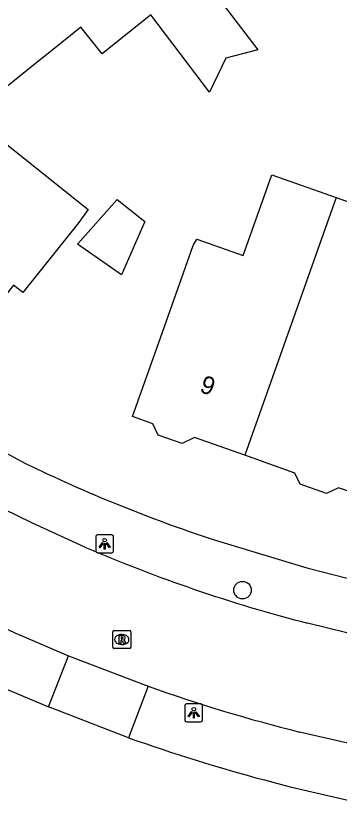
# Model space of a CAD drawing. Extents: x 161354 to 161876, y 382161 to 382804.
# Drawn here: x 161529.82 to 161547.84, y 382263.36 to 382307.76 of the extents above; entities that cross this region are included whole.
import ezdxf

# ---------------------------------------------------------------- set-up
doc = ezdxf.new("R2010")
doc.units = 0
for name, color, linetype in [('IMGEO_Boom', 7, 'Continuous'), ('IMGEO_Lichtpunt', 7, 'Continuous'), ('IMGEO_Pand', 7, 'Continuous'), ('IMGEO_Pand_nummerreeks', 7, 'Continuous'), ('IMGEO_Rijbaan_lokaal_open', 7, 'Continuous'), ('IMGEO_Rioolput', 7, 'Continuous'), ('IMGEO_Voetpad_open', 7, 'Continuous')]:
    doc.layers.add(name, color=color, linetype=linetype)

msp = doc.modelspace()

# ---------------------------------------------------------------- linework, layer by layer
at = {"layer": 'IMGEO_Boom'}
msp.add_circle((161542.46, 382275.697), 0.489, dxfattribs=at)
at = {"layer": 'IMGEO_Lichtpunt'}
for p, q in [((161534.268, 382278.688), (161534.268, 382277.881)), ((161534.268, 382278.688), (161534.268, 382277.881)), ((161535.17, 382278.783), (161534.362, 382278.783)), ((161535.17, 382278.783), (161534.362, 382278.783)), ((161535.264, 382277.881), (161535.264, 382278.688)), ((161535.264, 382277.881), (161535.264, 382278.688)), ((161534.362, 382277.787), (161535.17, 382277.787)), ((161534.362, 382277.787), (161535.17, 382277.787)), ((161540.14, 382269.341), (161539.332, 382269.341)), ((161540.14, 382269.341), (161539.332, 382269.341)), ((161539.238, 382269.246), (161539.238, 382268.439)), ((161539.238, 382269.246), (161539.238, 382268.439)), ((161540.234, 382268.439), (161540.234, 382269.246)), ((161540.234, 382268.439), (161540.234, 382269.246)), ((161539.332, 382268.345), (161540.14, 382268.345)), ((161539.332, 382268.345), (161540.14, 382268.345))]:
    msp.add_line(p, q, dxfattribs=at)
for points in [[(161534.642, 382278.352), (161534.681, 382278.324), (161534.493, 382278.062), (161534.455, 382278.089), (161534.642, 382278.352)], [(161534.744, 382278.304), (161534.791, 382278.304), (161534.791, 382277.982), (161534.744, 382277.982), (161534.744, 382278.304)], [(161534.854, 382278.324), (161534.892, 382278.351), (161535.079, 382278.089), (161535.04, 382278.061), (161534.854, 382278.324)], [(161539.612, 382268.91), (161539.651, 382268.882), (161539.463, 382268.62), (161539.425, 382268.647), (161539.612, 382268.91)], [(161539.714, 382268.862), (161539.761, 382268.862), (161539.761, 382268.54), (161539.714, 382268.54), (161539.714, 382268.862)], [(161539.824, 382268.882), (161539.862, 382268.909), (161540.049, 382268.647), (161540.01, 382268.619), (161539.824, 382268.882)]]:
    msp.add_lwpolyline(points, dxfattribs=at)
for centre in [(161534.767, 382278.486), (161539.737, 382269.044)]:
    msp.add_circle(centre, 0.0994, dxfattribs=at)
for centre, start, end in [((161534.362, 382278.688), 90, 180), ((161534.362, 382278.688), 90, 180), ((161535.17, 382278.688), 0, 90), ((161535.17, 382278.688), 0, 90), ((161534.362, 382277.881), 180, 270), ((161534.362, 382277.881), 180, 270), ((161535.17, 382277.881), 270, 0), ((161535.17, 382277.881), 270, 360), ((161539.332, 382269.246), 90, 180), ((161539.332, 382269.246), 90, 180), ((161540.14, 382269.246), 0, 90), ((161540.14, 382269.246), 0, 90), ((161539.332, 382268.439), 180, 270), ((161539.332, 382268.439), 180, 270), ((161540.14, 382268.439), 270, 0), ((161540.14, 382268.439), 270, 360)]:
    msp.add_arc(centre, 0.0946, start, end, dxfattribs=at)
at = {"layer": 'IMGEO_Pand'}
for points in [[(161543.947, 382317.901), (161540.508, 382315.776), (161541.12, 382314.787), (161541.541, 382314.106), (161542.303, 382312.873), (161540.652, 382311.847), (161541.072, 382311.228), (161539.937, 382310.312), (161543.303, 382305.867), (161541.52, 382305.408), (161540.611, 382303.498), (161537.338, 382307.819)], [(161537.338, 382307.819), (161534.623, 382305.648), (161533.443, 382307.123), (161531.709, 382305.736), (161530.821, 382305.026), (161528.353, 382303.052), (161528.216, 382302.943)], [(161528.461, 382301.243), (161533.848, 382296.958), (161533.32, 382296.223), (161530.209, 382292.308), (161529.675, 382292.733), (161526.941, 382289.292), (161517.353, 382296.911)], [(161542.582, 382283.225), (161539.787, 382284.215), (161539.082, 382283.879), (161537.751, 382284.351), (161537.45, 382284.984), (161536.323, 382285.383), (161537.993, 382290.096), (161539.711, 382294.946), (161539.91, 382295.288), (161542.49, 382294.374), (161544.089, 382298.888), (161547.675, 382297.617)], [(161535.705, 382293.299), (161533.261, 382295.006), (161535.469, 382297.513), (161537.017, 382296.273), (161535.705, 382293.299)], [(161547.675, 382297.617), (161542.582, 382283.225)], [(161547.675, 382297.617), (161551.015, 382296.434), (161550.47, 382294.897), (161550.288, 382294.382), (161552.401, 382293.633), (161552.498, 382293.908), (161555.344, 382292.899)], [(161554.609, 382289.153), (161552.505, 382280.471), (161548.799, 382281.783), (161548.572, 382281.142), (161547.811, 382281.412), (161547.14, 382281.092), (161545.678, 382281.61), (161545.38, 382282.234), (161542.582, 382283.225)]]:
    msp.add_lwpolyline(points, dxfattribs=at)
at = {"layer": 'IMGEO_Rijbaan_lokaal_open'}
for points in [[(161533.664, 382278.103), (161530.701, 382279.454), (161529.14, 382280.212), (161524.776, 382282.525), (161521.208, 382284.63)], [(161555.781, 382271.717), (161550.838, 382272.695), (161550.402, 382272.793), (161546.074, 382273.855)], [(161530.104, 382273.158), (161532.749, 382272.019)], [(161532.749, 382272.019), (161537.201, 382270.326)], [(161562.662, 382264.762), (161555.961, 382265.643), (161551.101, 382266.526), (161545.644, 382267.772)]]:
    msp.add_lwpolyline(points, dxfattribs=at)
for centre, radius, start, end in [((161575.363, 382373.581), 110.151, 239.33535, 245.73958), ((161566.952, 382355.098), 83.882, 246.61937, 255.58801), ((161567.322, 382354.666), 89.557, 250.3467, 255.99227)]:
    msp.add_arc(centre, radius, start, end, dxfattribs=at)
at = {"layer": 'IMGEO_Rioolput'}
for p, q in [((161535.221, 382272.513), (161535.221, 382273.365)), ((161535.296, 382273.439), (161536.148, 382273.439)), ((161536.222, 382273.365), (161536.222, 382272.513)), ((161535.709, 382273.219), (161535.734, 382273.219)), ((161536.148, 382272.439), (161535.296, 382272.439)), ((161535.732, 382272.659), (161535.707, 382272.659))]:
    msp.add_line(p, q, dxfattribs=at)
for points in [[(161535.221, 382272.513), (161535.221, 382273.365)], [(161535.296, 382273.439), (161536.148, 382273.439)], [(161536.222, 382273.365), (161536.222, 382272.513)], [(161535.81, 382273.137), (161535.558, 382273.139), (161535.558, 382272.739)], [(161535.558, 382272.739), (161535.682, 382272.739), (161535.682, 382272.901), (161535.693, 382272.901)], [(161535.736, 382273.058), (161535.682, 382273.058), (161535.682, 382272.977)], [(161535.682, 382272.977), (161535.734, 382272.977)], [(161535.74, 382272.872), (161535.811, 382272.739), (161535.951, 382272.739), (161535.886, 382272.865)], [(161536.148, 382272.439), (161535.296, 382272.439)]]:
    msp.add_lwpolyline(points, dxfattribs=at)
for centre, radius, start, end in [((161535.298, 382273.363), 0.0765, 91.552, 178.448), ((161535.298, 382273.363), 0.0765, 91.552, 178.448), ((161536.146, 382273.363), 0.0765, 1.552, 88.448), ((161536.146, 382273.363), 0.0765, 1.552, 88.448), ((161535.692, 382272.848), 0.0533, 26.0293, 88.6989), ((161535.718, 382273.166), 0.19, 274.7715, 282.9687), ((161535.742, 382272.962), 0.0964, 77.0061, 93.1865), ((161535.756, 382273.019), 0.0378, 276.6634, 79.6772), ((161535.809, 382273.027), 0.109, 350.3612, 89.416), ((161535.807, 382273.027), 0.112, 277.5842, 350.9817), ((161535.791, 382272.812), 0.108, 29.5134, 73.7905), ((161535.298, 382272.515), 0.0765, 181.552, 268.448), ((161535.298, 382272.515), 0.0765, 181.552, 268.448), ((161536.146, 382272.515), 0.0765, 271.552, 358.448), ((161536.146, 382272.515), 0.0765, 271.552, 358.448)]:
    msp.add_arc(centre, radius, start, end, dxfattribs=at)
for centre, major_axis, ratio, start_param, end_param in [((161535.708, 382272.939), (-0.387, 0.002), 0.722429, 4.712389, 7.853982), ((161535.733, 382272.939), (-0.39, 0.002), 0.717154, 1.570796, 4.712389)]:
    msp.add_ellipse(centre, major_axis=major_axis, ratio=ratio, start_param=start_param, end_param=end_param, dxfattribs=at)
at = {"layer": 'IMGEO_Voetpad_open'}
for points in [[(161520.54, 382288.316), (161525.389, 382285.441), (161530.352, 382282.768)], [(161540.817, 382278.523), (161546.054, 382276.944), (161551.353, 382275.587)], [(161531.625, 382269.181), (161532.749, 382272.019)], [(161528.526, 382270.477), (161531.625, 382269.181)], [(161537.201, 382270.326), (161536.103, 382267.455)], [(161536.103, 382267.455), (161531.625, 382269.181)]]:
    msp.add_lwpolyline(points, dxfattribs=at)
for centre, radius, start, end in [((161567.389, 382359.053), 84.801, 244.1027, 251.73863), ((161568.859, 382359.195), 97.413, 250.35082, 259.68483)]:
    msp.add_arc(centre, radius, start, end, dxfattribs=at)

# ---------------------------------------------------------------- texts
at = {"layer": 'IMGEO_Pand_nummerreeks'}
msp.add_text('9', height=1, rotation=340.9769, dxfattribs=at).set_placement((161540.014, 382286.777))

doc.saveas('drawing.dxf')
